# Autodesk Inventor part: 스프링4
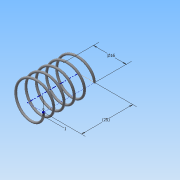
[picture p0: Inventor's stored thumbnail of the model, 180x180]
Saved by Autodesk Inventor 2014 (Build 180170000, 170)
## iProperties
Created: 2015-06
Part Number: 스프링4
Material: 강철, 연강
Document SubType Name: Modeling
Designer: Administrator
Density: 7.86 g/cm^3
Appearance: 강철
Mass: 1.52988 g
Surface Area: 7.87024 cm^2
Volume: 0.194641 cm^3
Author: Administrator
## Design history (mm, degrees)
sketch "스케치1"
  geometry: L1 (0, 0)-(8, 0); L2 (8, 0)-(8, 14.5); L3 (8, 14.5)-(0, 14.5); L4 (0, 14.5)-(0, 0); C1 r 0.5 at (8, 0)
  constraints: 8 end point, 2 parallel, 1 centre point, 1 coincident, 1 horizontal, 1 perpendicular
  dimensions: "d0" = 14.5 distance of L1.end L2.end (derived); "d1" = 16 diameter of L2 L4; "d2" = 1 diameter of C1
feature "코일1" sketch "스케치1" pitch "d3" = 10; turns "d5" = 5; dims "d4" = 14.5 (= d0), "d6" = 0, angle "d7" = 90 deg, angle "d8" = 90 deg, "d9" = 0, "d10" = 0
sketch "스케치2"
  geometry: L1 (-8.5, 0)-(-7.5, 0) reference; 1 further point
  constraints: 1 horizontal alignment
extrude "돌출1" cut sketch "스케치2" stored distance "d11" = 10; taper "d12" = 0 deg
node "작업 평면1"
sketch "스케치3"
  geometry: L1 (-7.5, 0)-(-8.5, 0) reference; 1 further point
  constraints: 1 horizontal alignment
extrude "돌출2" cut sketch "스케치3" stored distance "d14" = 10; taper "d15" = 0 deg
node "솔리드1"
node "절단 모서리 투영1"
node "절단 모서리 투영2"
other parameters: "d13" = 14.5 (= d0)
